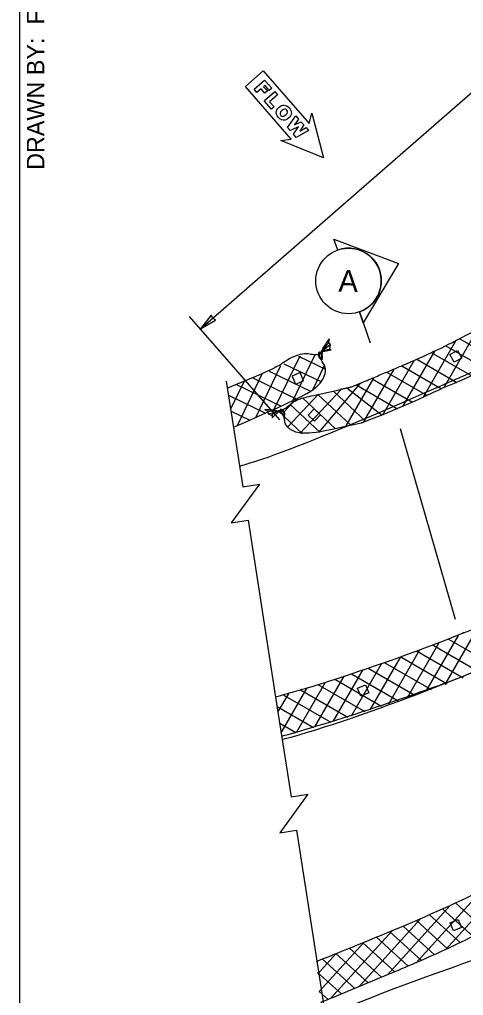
# Model space of a CAD drawing. Extents: x 99862 to 103680, y 99470 to 102076.
# Drawn here: x 99862 to 100269, y 100693 to 101587 of the extents above; entities that cross this region are included whole.
import ezdxf

# ---------------------------------------------------------------- set-up
doc = ezdxf.new("R2010")
doc.units = 0
for name, color, linetype in [('Level 1', 7, 'Continuous'), ('Level 15', 7, 'Continuous'), ('Level 20', 7, 'Continuous'), ('Level 3', 7, 'Continuous'), ('Level 4', 7, 'Continuous'), ('Level 62', 7, 'Continuous'), ('Level 9', 7, 'Continuous')]:
    doc.layers.add(name, color=color, linetype=linetype)

msp = doc.modelspace()

# ---------------------------------------------------------------- linework, layer by layer
at = {"layer": 'Level 1'}
msp.add_lwpolyline([(99862, 99999.5), (103151, 99999.5), (103151, 102075.5), (99862, 102075.5)], close=True, dxfattribs=at)
at = {"layer": 'Level 15'}
msp.add_line((100027.71, 101303.69), (100752.94, 101936.18), dxfattribs=at)
for points in [[(100100.45, 101220.28), (100017.7, 101315.16)], [(100051.44, 101255.92), (100066.61, 101158.87), (100081.91, 101161.27), (100056.09, 101125.88), (100071.39, 101128.27), (100096.69, 100966.36)], [(100095.81, 100972.05), (100110.97, 100875), (100126.27, 100877.39), (100100.45, 100842.01), (100115.75, 100844.4), (100148.3, 100636.15)]]:
    msp.add_lwpolyline(points, dxfattribs=at)
msp.add_lwpolyline([(100027.71, 101303.69), (100041.59, 101311.7), (100039.01, 101313.54), (100037.53, 101316.35)], close=True, dxfattribs=at)
at = {"layer": 'Level 20'}
for p, q in [((100153.58, 101375.93), (100150.07, 101385.94)), ((100150.07, 101385.94), (100209.25, 101363.7)), ((100153.58, 101375.93), (100150.07, 101385.94)), ((100150.07, 101385.94), (100209.25, 101363.7)), ((100209.25, 101363.7), (100177, 101309.33)), ((100209.25, 101363.7), (100177, 101309.33)), ((100177, 101309.33), (100173.48, 101319.33)), ((100173.48, 101319.33), (100183.43, 101291.03)), ((100177, 101309.33), (100173.48, 101319.33)), ((100173.48, 101319.33), (100183.43, 101291.03)), ((100210.96, 101212.55), (100261.12, 101037.56))]:
    msp.add_line(p, q, dxfattribs=at)
for points in [[(100140.53, 101460.29), (100101.32, 101476.41), (100111.01, 101477.67), (100069, 101525.83), (100085.33, 101540.07), (100127.34, 101491.91), (100129.9, 101501.33), (100140.53, 101460.29)], [(100140.53, 101460.29), (100101.32, 101476.41), (100111.01, 101477.67), (100069, 101525.83), (100085.33, 101540.07), (100127.34, 101491.91), (100129.9, 101501.33), (100140.53, 101460.29)], [(100086.65, 101531.59), (100093.1, 101524.2), (100090.88, 101522.26), (100087.01, 101526.7), (100085.72, 101525.57), (100089.1, 101521.69), (100086.88, 101519.75), (100083.5, 101523.64), (100079.62, 101520.25), (100077.04, 101523.21), (100086.65, 101531.59)], [(100086.65, 101531.59), (100093.1, 101524.2), (100090.88, 101522.26), (100087.01, 101526.7), (100085.72, 101525.57), (100089.1, 101521.69), (100086.88, 101519.75), (100083.5, 101523.64), (100079.62, 101520.25), (100077.04, 101523.21), (100086.65, 101531.59)], [(100095.82, 101521.08), (100098.4, 101518.12), (100091.19, 101511.84), (100095.22, 101507.21), (100092.81, 101505.12), (100086.2, 101512.7), (100095.82, 101521.08)], [(100095.82, 101521.08), (100098.4, 101518.12), (100091.19, 101511.84), (100095.22, 101507.21), (100092.81, 101505.12), (100086.2, 101512.7), (100095.82, 101521.08)], [(100109.18, 101506.13), (100110.09, 101504.92), (100110.72, 101503.72), (100111.06, 101502.51), (100111.12, 101501.29), (100110.9, 101500.1), (100110.42, 101498.96), (100109.66, 101497.87), (100108.63, 101496.83), (100106.96, 101495.63), (100105.36, 101494.98), (100103.79, 101494.83), (100102.24, 101495.15), (100100.74, 101495.96), (100099.3, 101497.3), (100098.13, 101498.91), (100097.47, 101500.45), (100097.3, 101502.01), (100097.61, 101503.62), (100097.95, 101504.43), (100098.44, 101505.22), (100099.07, 101506), (100099.85, 101506.74), (100101.03, 101507.63), (100102.23, 101508.25), (100103.44, 101508.58), (100104.67, 101508.64), (100105.88, 101508.42), (100107.03, 101507.93), (100108.13, 101507.16), (100109.18, 101506.13)], [(100109.18, 101506.13), (100110.09, 101504.92), (100110.72, 101503.72), (100111.06, 101502.51), (100111.12, 101501.29), (100110.9, 101500.1), (100110.42, 101498.96), (100109.66, 101497.87), (100108.63, 101496.83), (100106.96, 101495.63), (100105.36, 101494.98), (100103.79, 101494.83), (100102.24, 101495.15), (100100.74, 101495.96), (100099.3, 101497.3), (100098.13, 101498.91), (100097.47, 101500.45), (100097.3, 101502.01), (100097.61, 101503.62), (100097.95, 101504.43), (100098.44, 101505.22), (100099.07, 101506), (100099.85, 101506.74), (100101.03, 101507.63), (100102.23, 101508.25), (100103.44, 101508.58), (100104.67, 101508.64), (100105.88, 101508.42), (100107.03, 101507.93), (100108.13, 101507.16), (100109.18, 101506.13)], [(100107.54, 101503.21), (100106.96, 101504.2), (100106.08, 101504.88), (100105.04, 101505.1), (100103.82, 101504.76), (100102.43, 101503.79), (100101.27, 101502.54), (100100.78, 101501.39), (100100.86, 101500.32), (100101.44, 101499.34), (100102.34, 101498.61), (100103.37, 101498.39), (100104.6, 101498.75), (100106.11, 101499.83), (100107.18, 101501.01), (100107.63, 101502.14), (100107.54, 101503.21)], [(100107.54, 101503.21), (100106.96, 101504.2), (100106.08, 101504.88), (100105.04, 101505.1), (100103.82, 101504.76), (100102.43, 101503.79), (100101.27, 101502.54), (100100.78, 101501.39), (100100.86, 101500.32), (100101.44, 101499.34), (100102.34, 101498.61), (100103.37, 101498.39), (100104.6, 101498.75), (100106.11, 101499.83), (100107.18, 101501.01), (100107.63, 101502.14), (100107.54, 101503.21)], [(100124.57, 101488.11), (100126.95, 101485.39), (100115.57, 101479.02), (100113.02, 101481.95), (100117.59, 101488.92), (100110.07, 101485.33), (100107.53, 101488.25), (100115.27, 101498.77), (100117.74, 101495.94), (100113.85, 101490.65), (100119.85, 101493.52), (100122.45, 101490.54), (100118.8, 101484.97), (100124.57, 101488.11)], [(100124.57, 101488.11), (100126.95, 101485.39), (100115.57, 101479.02), (100113.02, 101481.95), (100117.59, 101488.92), (100110.07, 101485.33), (100107.53, 101488.25), (100115.27, 101498.77), (100117.74, 101495.94), (100113.85, 101490.65), (100119.85, 101493.52), (100122.45, 101490.54), (100118.8, 101484.97), (100124.57, 101488.11)]]:
    msp.add_lwpolyline(points, dxfattribs=at)
msp.add_circle((100163.53, 101347.63), 30, dxfattribs=at)
msp.add_circle((100163.53, 101347.63), 30, dxfattribs=at)
msp.add_arc((100163.53, 101347.63), 30, 289.36507, 109.3695, dxfattribs=at)
msp.add_arc((100163.53, 101347.63), 30, 289.36507, 109.3695, dxfattribs=at)
at = {"layer": 'Level 3'}
for points in [[(100256.43, 101280.21), (100263.5, 101283.94), (100267.23, 101276.87), (100260.16, 101273.14)], [(100119.23, 101263.58), (100111.87, 101260.45), (100115.01, 101253.09), (100122.37, 101256.22)], [(100126.48, 101224.68), (100131.98, 101230.48), (100137.79, 101224.97), (100132.28, 101219.17)], [(100171.81, 100974.61), (100179.2, 100977.67), (100182.26, 100970.28), (100174.87, 100967.22)], [(100256.53, 100759.34), (100263.86, 100762.54), (100267.06, 100755.21), (100259.73, 100752.01)]]:
    msp.add_lwpolyline(points, close=True, dxfattribs=at)
at = {"layer": 'Level 4'}
for p, q in [((100250.9, 101249.81), (100281.62, 101303.03)), ((100231.91, 101240.92), (100261.77, 101292.65)), ((100265.53, 101294.57), (100302.66, 101273.13)), ((100213.22, 101232.57), (100242.55, 101283.36)), ((100239.32, 101281.99), (100276.47, 101260.54)), ((100252.71, 101288.12), (100289.75, 101266.73)), ((100095.5, 101230.08), (100119.11, 101279.13)), ((100112.47, 101237.67), (100132.59, 101279.48)), ((100117.54, 101278.67), (100142.53, 101266.65)), ((100194.98, 101224.97), (100223.78, 101274.86)), ((100226.01, 101275.82), (100262.69, 101254.64)), ((100078.58, 101222.59), (100101.5, 101270.21)), ((100090.63, 101264.99), (100129.15, 101246.45)), ((100104.26, 101271.75), (100138.7, 101255.17)), ((100130.43, 101247.32), (100141.47, 101270.26)), ((100177.22, 101218.21), (100205.22, 101266.71)), ((100198.77, 101263.83), (100235.53, 101242.61)), ((100212.34, 101269.85), (100248.77, 101248.82)), ((100055.48, 101229.93), (100067.8, 101255.54)), ((100061.68, 101215.14), (100084.41, 101262.37)), ((100075.79, 101258.81), (100116.2, 101239.37)), ((100161.48, 101214.94), (100186.6, 101258.45)), ((100185.16, 101257.84), (100222.14, 101236.49)), ((100060.82, 101252.7), (100101.91, 101232.93)), ((100118.93, 101207.98), (100156.92, 101248.55)), ((100136.15, 101208.82), (100174.82, 101254.2)), ((100149.73, 101246.69), (100179.35, 101218.95)), ((100162, 101249.59), (100194.45, 101224.76)), ((100171.06, 101252.12), (100208.46, 101230.53)), ((100053.64, 101242.84), (100087.51, 101226.54)), ((100104.6, 101227.79), (100113.8, 101237.62)), ((100107.69, 101213.54), (100136.04, 101243.8)), ((100114.71, 101238.43), (100115.19, 101238.12)), ((100121.24, 101240.49), (100151.47, 101212.18)), ((100135.38, 101243.68), (100165.65, 101215.34)), ((100055.93, 101228.42), (100073.08, 101220.16)), ((100089.15, 101228.6), (100100.33, 101228.51)), ((100089.89, 101226), (100100.18, 101228.4)), ((100110.03, 101234.55), (100137.27, 101209.04)), ((100104.46, 101223.32), (100121.21, 101207.63)), ((100234.76, 100971.78), (100264.2, 101022.75)), ((100252.18, 100977.94), (100282.29, 101030.09)), ((100268.38, 101025.68), (100268.62, 101025.55)), ((100217.48, 100965.84), (100246.34, 101015.83)), ((100240.97, 101013.8), (100283.19, 100989.42)), ((100255.11, 101019.41), (100297.18, 100995.13)), ((100200.31, 100960.1), (100228.68, 101009.23)), ((100226.35, 101008.38), (100268.62, 100983.98)), ((100166.27, 100949.14), (100193.81, 100996.85)), ((100183.24, 100954.53), (100211.33, 101003.19)), ((100196.64, 100997.82), (100239.11, 100973.3)), ((100211.33, 101003.19), (100253.96, 100978.58)), ((100149.41, 100943.95), (100176.58, 100991)), ((100166.33, 100987.61), (100208.98, 100962.98)), ((100181.56, 100992.67), (100224.12, 100968.1)), ((100116.16, 100934.35), (100142.52, 100980)), ((100132.68, 100938.96), (100159.48, 100985.38)), ((100135.33, 100977.79), (100178.34, 100952.96)), ((100150.93, 100982.64), (100193.72, 100957.93)), ((100098.87, 100952.41), (100109.05, 100970.04)), ((100101.83, 100933.52), (100125.71, 100974.89)), ((100103.48, 100968.47), (100147.14, 100943.26)), ((100119.53, 100973.06), (100162.82, 100948.06)), ((100098.04, 100957.75), (100131.29, 100938.56)), ((100100.42, 100942.52), (100115.24, 100933.96)), ((100252.36, 100734.8), (100315.23, 100804.13)), ((100225.17, 100722.67), (100284.62, 100788.24)), ((100199.18, 100711.87), (100256.4, 100774.98)), ((100249.88, 100772.07), (100277.66, 100746.88)), ((100261.82, 100777.44), (100289.11, 100752.7)), ((100173.22, 100701.11), (100229.6, 100763.29)), ((100237.82, 100766.81), (100266.06, 100741.21)), ((100213.5, 100756.47), (100242.4, 100730.26)), ((100225.68, 100761.62), (100254.29, 100735.68)), ((100147.12, 100690.18), (100203.37, 100752.23)), ((100189.01, 100746.27), (100218.28, 100719.74)), ((100201.27, 100751.35), (100230.41, 100724.94)), ((100136.68, 100696.53), (100177.5, 100741.55)), ((100164.37, 100736.22), (100193.71, 100709.61)), ((100176.71, 100741.23), (100206, 100714.67)), ((100135.31, 100712.88), (100151.93, 100731.21)), ((100151.99, 100731.24), (100181.45, 100704.53)), ((100139.59, 100726.29), (100169.21, 100699.43)), ((100135.19, 100714.08), (100156.99, 100694.32)), ((100136.68, 100696.53), (100144.77, 100689.19))]:
    msp.add_line(p, q, dxfattribs=at)
for points in [[(100155.7, 101248.22), (100156.53, 101248.44), (100157.38, 101248.67)], [(100157.38, 101248.67), (100165.2, 101250.17), (100166.56, 101250.71)], [(100176.03, 101217.73), (100175.53, 101217.54), (100175.03, 101217.42)]]:
    msp.add_open_spline(points, degree=2, dxfattribs=at)
at = {"layer": 'Level 9'}
for p, q in [((100145.06, 101291.26), (100138.37, 101282.31)), ((100146.68, 101289.1), (100138.55, 101282.36))]:
    msp.add_line(p, q, dxfattribs=at)
for points in [[(100145.63, 101294.66), (100145.06, 101291.26), (100146.68, 101289.1), (100145.94, 101285.13), (100147.48, 101284.05), (100138.43, 101282.42)], [(100086.56, 101229.96), (100089.15, 101228.6), (100089.89, 101226), (100093.5, 101224.19), (100093.44, 101222.31), (100100.2, 101228.53)]]:
    msp.add_lwpolyline(points, dxfattribs=at)
for points, degree in [([(100914.83, 101858.37), (100834.8, 101768.52), (100713.9, 101597.76), (100624.04, 101489.68), (100391.29, 101318.55), (100354.25, 101297.68), (100106.48, 101188.69), (100064.25, 101178.05)], 3), ([(100227.6, 101276.52), (100237.11, 101281.13), (100255.03, 101288.02), (100379.64, 101356.95), (100533.97, 101468.53), (100619.28, 101553.28), (100695.66, 101645.17), (100759.14, 101726.3), (100788.25, 101773.29), (100793.45, 101781.01)], 3), ([(100825.38, 101768.41), (100816.12, 101755.79), (100779.25, 101697.08), (100742.19, 101646.43), (100708.96, 101605.62), (100650.91, 101532.78), (100614.11, 101497.53), (100553.28, 101435.17), (100395.38, 101324.28), (100286.61, 101263.38), (100254.05, 101251.28)], 3), ([(100900.02, 101393.47), (100851.05, 101343.72), (100817.29, 101310.18), (100646.97, 101189.11), (100551.95, 101135.12), (100404.86, 101037.23), (100179.06, 100947.95), (100103.39, 100927.32)], 3), ([(101142.53, 101324.77), (101030.43, 101179.16), (100966.3, 101105.92), (100844.53, 100991.21), (100709.32, 100905.3), (100580.52, 100837.47), (100320.24, 100738.93), (100199.28, 100698.26), (100142.42, 100673.76)], 3), ([(100145.63, 101294.66), (100137.37, 101282.81), (100139.71, 101279.43), (100139.13, 101274.13), (100135.65, 101279.03), (100136.23, 101281.01)], 2), ([(100058.12, 101213.64), (100114.23, 101238.27), (100132.21, 101247.39), (100141.49, 101258.25), (100143.02, 101267.63), (100140.44, 101272.02), (100138.17, 101275.03), (100138.87, 101278.56), (100139.73, 101281.02), (100139.55, 101281.99), (100138.29, 101281.76), (100134.61, 101279.39), (100128.86, 101280.32), (100123.91, 101281.23), (100114.93, 101279.7), (100103.1, 101272.42), (100094.66, 101266.4), (100052.54, 101249.27)], 3), ([(100136.23, 101281.01), (100136.75, 101283.09), (100138.06, 101281.99), (100139.4, 101275.19), (100137.05, 101277.51), (100136.77, 101282.79), (100145.94, 101285.13)], 2), ([(100166.56, 101250.71), (100208.78, 101268.35), (100227.6, 101276.52)], 2), ([(100096.66, 100966.56), (100099.96, 100967.48), (100103.25, 100968.4), (100151.36, 100981.83), (100297.18, 101033.24), (100402.99, 101090.35), (100502.27, 101156.86), (100586.12, 101216.7), (100627.48, 101253.64), (100634.66, 101260.36)], 3), ([(100175.03, 101217.42), (100151.4, 101212.17), (100126.77, 101206.61), (100112.7, 101209.06), (100105.54, 101215.3), (100104.72, 101220.33), (100104.56, 101224.11), (100101.77, 101226.37), (100099.54, 101227.72), (100099.05, 101228.58), (100100.17, 101229.21), (100104.52, 101229.74), (100108.83, 101233.53), (100112.43, 101236.58), (100117.12, 101239.12), (100129.54, 101242.61), (100146.15, 101245.67), (100166.56, 101250.71)], 3), ([(100254.05, 101251.28), (100244.29, 101246.73), (100204.9, 101228.13), (100175.03, 101217.42)], 3), ([(100665.93, 101241.92), (100652.82, 101232.11), (100597.13, 101182.98), (100547.25, 101144.89), (100503.82, 101115.17), (100427.52, 101061.74), (100382.25, 101038.35), (100306.25, 100995.77), (100157.19, 100945.51), (100102.64, 100930.39)], 3), ([(100087.13, 101230.15), (100100.55, 101229.54), (100101.81, 101225.71), (100106.38, 101222.96), (100104.58, 101228.7), (100102.66, 101229.43)], 3), ([(100102.66, 101229.43), (100100.69, 101230.27), (100100.77, 101228.57), (100105.38, 101223.39), (100104.95, 101226.66), (100100.91, 101230.07), (100092.57, 101224.38)], 2), ([(100134.24, 100724.17), (100135.36, 100724.61), (100192.02, 100747.07), (100286.62, 100787.84), (100334.85, 100815.21), (100343.28, 100820.26)], 3), ([(100369.96, 100795.63), (100355.07, 100788.81), (100290.26, 100752.56), (100233.46, 100725.87), (100184.73, 100705.99), (100139.79, 100687.1), (100137.83, 100686.28)], 3)]:
    msp.add_open_spline(points, degree=degree, dxfattribs=at)

# ---------------------------------------------------------------- texts
at = {"layer": 'Level 20'}
msp.add_text('A', height=20, rotation=358.98424, dxfattribs=at).set_placement((100154.11, 101337.8))
at = {"layer": 'Level 62'}
msp.add_text('DRAWN BY:  FERN LIDDELL', height=16, rotation=90, dxfattribs=at).set_placement((99884.71, 101449.37))

doc.saveas('drawing.dxf')
